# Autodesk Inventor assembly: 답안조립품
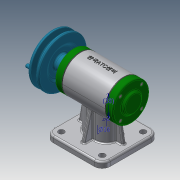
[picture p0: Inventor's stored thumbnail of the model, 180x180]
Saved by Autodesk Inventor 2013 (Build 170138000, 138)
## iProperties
Created: 2021-08
Part Number: 답안조립품
Document SubType Name: Assembly
Designer: user
Author: user
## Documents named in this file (20)
- C:\Users\user\Desktop\610806V1032\답안조립품.iam
- C:\Users\user\Desktop\610806V1032\본체.ipt
- C:\Users\user\Desktop\610806V1032\오일 실 12 22 7.ipt
- 오일 실 12 22 7.ipt
- C:\Users\user\Desktop\610806V1032\와셔.ipt
- C:\Users\user\Desktop\610806V1032\키 4x4x18.ipt
- 키 4x4x18.ipt
- C:\Users\user\Desktop\610806V1032\편심축.ipt
- C:\Users\user\Desktop\610806V1032\V-벨트풀리.ipt
- C:\Users\user\Desktop\610806V1032\가변스프링.ipt
- C:\Users\user\Desktop\610806V1032\개스킷.ipt
- C:\Users\user\Desktop\610806V1032\뒤커버.ipt
- C:\Users\user\Desktop\610806V1032\멈춤나사 M3x8.ipt
- C:\Users\user\Desktop\610806V1032\베어링 6201.ipt
- C:\Users\user\Desktop\610806V1032\베어링 6202.ipt
- C:\Users\user\Desktop\610806V1032\본체커버.ipt
- C:\Users\user\Desktop\610806V1032\볼트 M3x0.5x8.ipt
- C:\Users\user\Desktop\610806V1032\볼트 M6 x 12.ipt
- C:\Users\user\Desktop\610806V1032\슬라이드.ipt
- C:\Users\user\Desktop\610806V1032\앞커버.ipt
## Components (4 placed, 3 different names)
1. V-벨트풀리:1
2. 가변스프링:1
3. 개스킷:1
4. 개스킷:2
